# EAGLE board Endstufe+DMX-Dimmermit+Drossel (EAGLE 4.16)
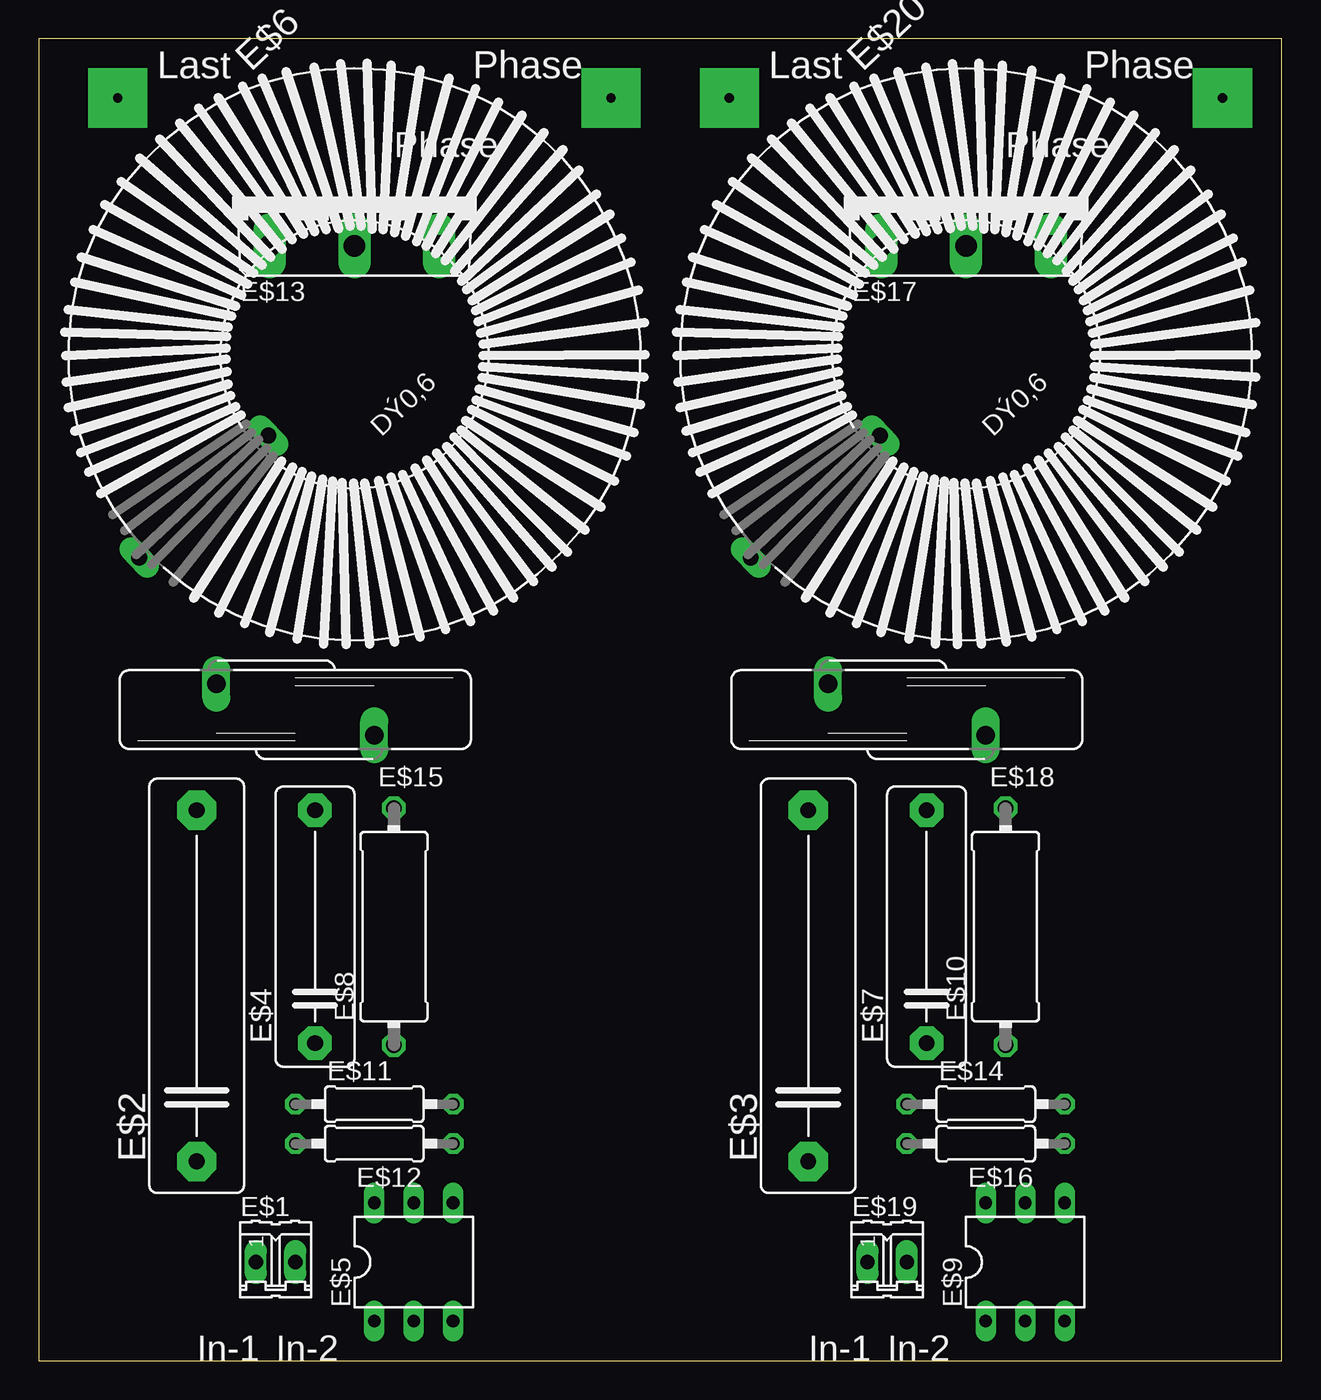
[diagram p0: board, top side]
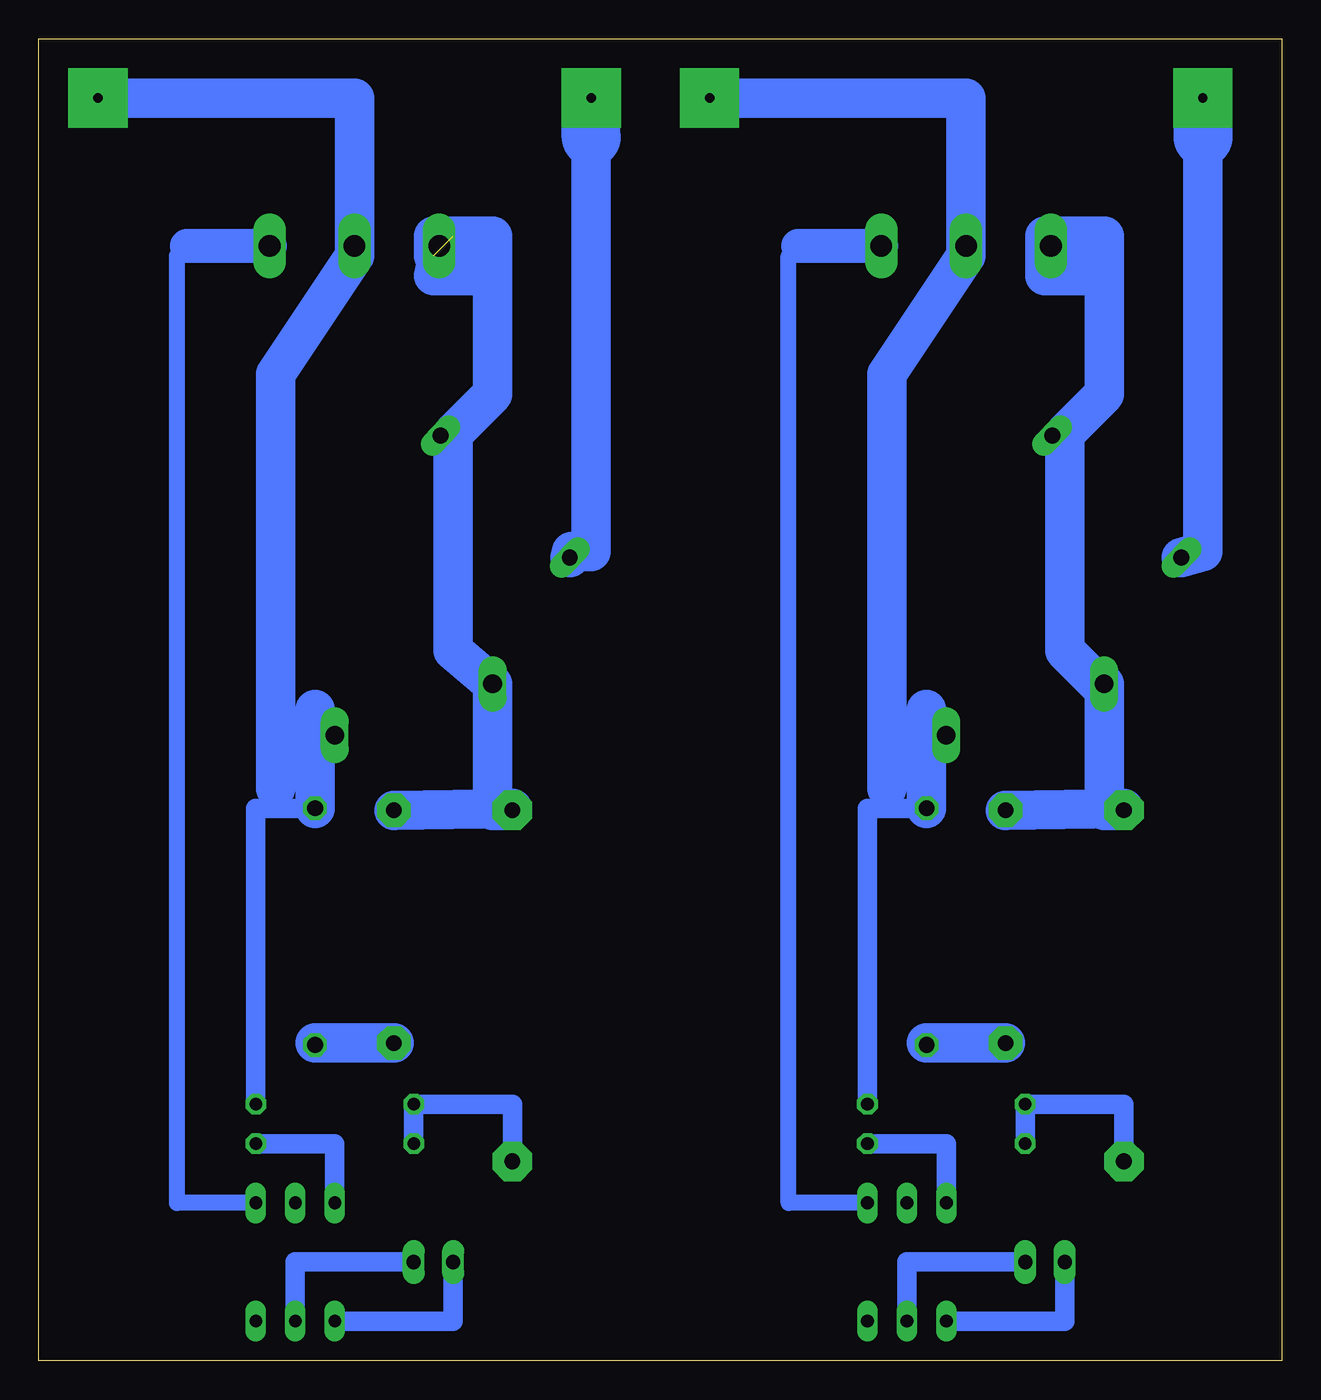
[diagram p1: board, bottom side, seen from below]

Size 80.01 x 85.09 mm. Coordinates in mm from the lower left corner, seen from the top.
Outline: 80.01,0 80.01,85.09 0,85.09 0,0 80.01,0
Copper layers (1*16): Top 0.035mm / dielectric 1.5mm / Bottom 0.035mm
Design rules "default": minimum track width 10mil, minimum drill 24mil, track to track 8mil, track to pad 8mil, pad to pad 8mil, via to via 8mil, smd to smd 8mil, copper to edge 40mil, drill to drill 8mil, minimum pad ring 10mil, minimum via ring 8mil, stop-mask expansion 4mil, vias tented up to drill 0mil, thermal gap 10mil

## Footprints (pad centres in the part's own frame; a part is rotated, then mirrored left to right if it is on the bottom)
02P = drill 0.914 long: 1 -1.27,0; 2 1.27,0
C22.5B6 = drill 1.016 pad 2.54 octagon: 1 -11.303,0; 2 11.303,0
C15B5 = drill 1.016 pad 2.159 octagon: 1 -7.493,0; 2 7.493,0
DIL06 = drill 0.813 long: 1 -2.54,-3.81; 2 0,-3.81; 3 2.54,-3.81; 4 2.54,3.81; 5 0,3.81; 6 -2.54,3.81
ED38 = drill 1.016 long: 1 -19.05,0; 2 -7.62,0
0414/15 = drill 1.016 octagon: 1 -7.62,0; 2 7.62,0
0207/10 = drill 0.813 octagon: 1 -5.08,0; 2 5.08,0
TOP3S-2 = drill 1.397 long: A 0,-3.175; C -5.461,-3.175; G 5.461,-3.175
S20K275 = drill 1.194 long: 1 -1.651,-5.08; 2 1.651,5.08

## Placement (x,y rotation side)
E$1  [02P]  15.24,6.35 0 top
E$2  47nF  [C22.5B6]  10.16,24.13 90 top
E$3  47nF  [C22.5B6]  49.53,24.13 90 top
E$4  10 nF  [C15B5]  17.78,27.94 90 top
E$5  MOC3021  [DIL06]  24.13,6.35 0 top
E$6  Drossel  [ED38]  20.32,64.77 43.3 top
E$7  10 nF  [C15B5]  57.15,27.94 90 top
E$8  47 2W  [0414/15]  22.86,27.94 90 top
E$9  MOC3021  [DIL06]  63.5,6.35 0 top
E$10  47 2W  [0414/15]  62.23,27.94 90 top
E$11  470  [0207/10]  21.59,16.51 0 top
E$12  360  [0207/10]  21.59,13.97 180 top
E$13  BTA 26/600  [TOP3S-2]  20.32,74.93 0 top
E$14  470  [0207/10]  60.96,16.51 0 top
E$15  S20K300  [S20K275]  16.51,41.91 90 top
E$16  360  [0207/10]  60.96,13.97 180 top
E$17  BTA 26/600  [TOP3S-2]  59.69,74.93 0 top
E$18  S20K300  [S20K275]  55.88,41.91 90 top
E$19  [02P]  54.61,6.35 0 top
E$20  Drossel  [ED38]  59.69,64.77 43.3 top

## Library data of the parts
E$1 E$19 = con-amp-quick
E$2-E$4 E$7 = 0-test
E$5 E$9 = optocoupler
E$6 E$20 = inductors
E$8 E$10-E$12 E$14 E$16 = rcl
E$13 E$17 = triac
E$15 E$18 = varistor

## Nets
S$2: E$5.6 E$12.1
S$3: E$2.1 E$11.1 E$12.2
S$4: E$2.2 E$4.2 E$15.2
S$5: E$4.1
S$7: E$5.4 E$13.G
S$9: E$1.1 E$5.1
S$10: E$1.2 E$5.2
S$12: E$6.1
S$13: E$9.6 E$16.1
S$14: E$3.1 E$14.1 E$16.2
S$15: E$9.4 E$17.G
S$18: E$9.1 E$19.1
S$19: E$9.2 E$19.2
S$20: E$7.1
S$21: E$10.2 E$14.2 E$18.1
S$22: E$20.1
S$23: E$3.2 E$7.2 E$18.2
S$24: E$8.2 E$11.2
S$28: E$17.C

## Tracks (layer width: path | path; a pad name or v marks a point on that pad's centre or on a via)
S$1  (via drill 0.6 pad 3.81)
  other vias: 36.83,81.28
S$2
  Bottom 1.27: E$5.6 21.59,13.97 E$12.1
S$3
  Bottom 1.27: E$2.1 10.16,16.51 E$11.1 E$12.2
S$4
  Bottom 0.406: E$2.2 10.16,35.56
  Bottom 2.54: 12.7,69.85 15.24,69.85 15.24,72.39 11.43,72.39 11.43,62.23 13.97,59.69 13.97,45.72 11.81,43.56 E$15.2 11.43,35.43 E$2.2 | 10.16,35.56 E$4.2
S$5
  Bottom 2.54: E$4.1 22.86,20.45
S$6
  Bottom 2.54: 36.83,81.28 20.32,81.28 20.32,71.12 25.4,63.5
S$7
  Bottom 1.016: 31.11,71.75 31.75,71.12 31.75,10.16 E$5.4
  Bottom 2.184: E$13.G 31.11,71.75
S$8  (via drill 0.6 pad 3.81)
  other vias: 5.08,81.28
S$9
  Bottom 1.27: E$1.1 13.97,2.54 E$5.1
S$10
  Bottom 1.27: E$1.2 24.13,6.35 E$5.2
S$12
  Bottom 2.54: 5.08,81.28 5.08,80.01 5.08,52.07 E$6.1
  Bottom 3.81: 5.08,80.01 5.08,78.74
S$13
  Bottom 1.27: E$9.6 60.96,13.97 E$16.1
S$14
  Bottom 1.27: E$3.1 49.53,16.51 E$14.1 E$16.2
S$15
  Bottom 1.016: 70.48,71.75 71.12,71.12 71.12,10.16 E$9.4
  Bottom 2.184: E$17.G 70.48,71.75
S$16  (via drill 0.6 pad 3.81)
  other vias: 76.2,81.28
S$17  (via drill 0.6 pad 3.81)
  other vias: 44.45,81.28
S$18
  Bottom 1.27: E$19.1 53.34,2.54 E$9.1
S$19
  Bottom 1.27: E$19.2 63.5,6.35 E$9.2
S$20
  Bottom 2.54: E$7.1 62.23,20.45
S$21
  Bottom 0.406: 62.23,41.91 E$18.1
  Bottom 1.27: E$10.2 66.04,35.56 E$14.2
  Bottom 2.54: E$10.2 62.23,41.91
S$22
  Bottom 2.54: 44.45,78.74 44.45,52.07 45.72,52.07 E$20.1
  Bottom 3.81: 44.45,78.74 44.45,81.28
S$23  (1 unrouted)
  Bottom 0.406: E$3.2 49.53,35.56
  Bottom 2.54: 49.53,35.56 E$7.2 | E$3.2 50.8,35.43 E$18.2 53.34,45.72 53.34,59.69 50.8,62.23 50.8,72.39 54.61,72.39 54.61,71.12
S$24
  Bottom 1.27: E$8.2 26.67,35.56 E$11.2
  Bottom 2.54: E$8.2 22.86,41.91
S$25
  Bottom 2.54: 25.4,36.83 25.4,63.5
S$26
  Bottom 2.54: 76.2,81.28 59.69,81.28 59.69,71.12 64.77,63.5 64.77,36.83
S$28
  Bottom 2.54: E$17.C 54.61,69.85 52.07,69.85

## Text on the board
tPlace: Last | Phase | Last | Phase | Phase | Phase | In-1 | In-2 | In-1 | In-2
